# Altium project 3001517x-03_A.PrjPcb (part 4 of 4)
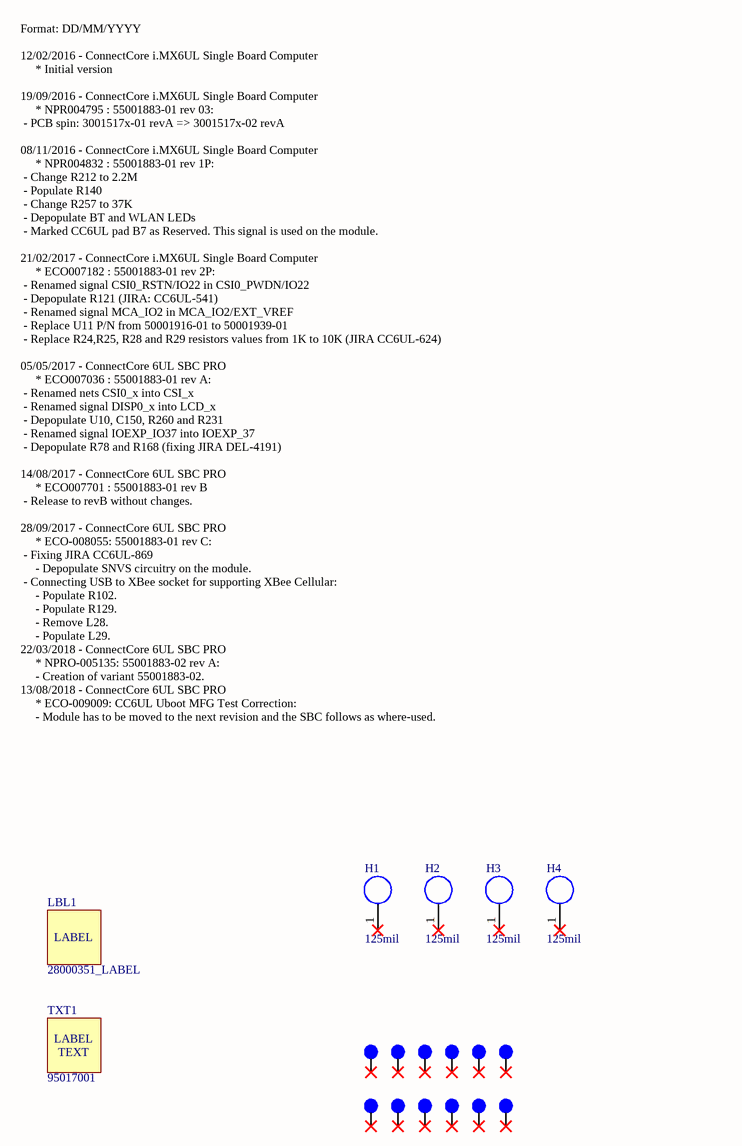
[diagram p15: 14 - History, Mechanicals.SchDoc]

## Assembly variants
55001883-01: not fitted C18 C19 C30 C31 C32 C33 C40 C48 C49 C50 C51 C52 C61 C80 C111 C114 C121 C147 C150 D3 D11 D12 J11 J13 J19 J20 J37 L28 Q5 R3 R5 R6 R18 R19 R20 R23 R24 R26 R27 R29 R41 R50 R56 R61 R62 R63 R67 R78 R80 R81 R82 R84 R90 R101 R118 R121 R130 R133 R134 R135 R136 R137 R145 R146 R151 R152 R162 R163 R164 R165 R167 R168 R172 R173 R174 R175 R176 R183 R184 R203 R205 R206 R207 R208 R209 R210 R211 R214 R215 R216 R217 R218 R219 R220 R221 R222 R223 R224 R226 R229 R230 R231 R232 R233 R234 R235 R236 R237 R238 R239 R243 R244 R245 R246 R250 R256 R259 R260 R263 R264 R269 R274 R275 U10
55001883-02: not fitted C18 C19 C30 C31 C32 C33 C40 C48 C49 C50 C51 C52 C61 C80 C111 C114 C121 C147 C150 D3 D11 D12 J11 J13 J19 J20 J37 L28 Q5 R3 R5 R6 R18 R19 R20 R23 R24 R26 R27 R29 R41 R50 R56 R61 R62 R63 R67 R78 R80 R81 R82 R84 R90 R101 R118 R121 R130 R133 R134 R135 R136 R137 R145 R146 R151 R152 R162 R163 R164 R165 R167 R168 R172 R173 R174 R175 R176 R183 R184 R203 R205 R206 R207 R208 R209 R210 R211 R214 R215 R216 R217 R218 R219 R220 R221 R222 R223 R224 R226 R229 R230 R231 R232 R233 R234 R235 R236 R237 R238 R239 R243 R244 R245 R246 R250 R256 R259 R260 R263 R264 R269 R274 R275 U10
